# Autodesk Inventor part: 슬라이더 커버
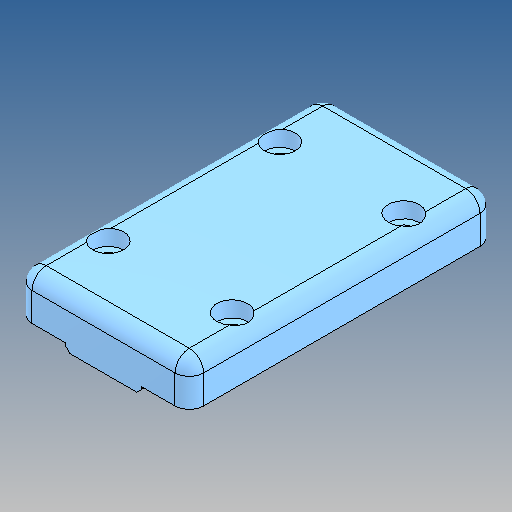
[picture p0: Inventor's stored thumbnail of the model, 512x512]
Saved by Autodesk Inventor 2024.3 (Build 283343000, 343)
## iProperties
Created: 2025-06
Part Number: 슬라이더 커버
Material: 알루미늄 6061
Document SubType Name: Modeling
Designer: user
Density: 2.7 g/cm^3
Appearance: 기본값
Author: jhkim
Sending System: Autodesk Inventor 2026
Preprocessor: ST-DEVELOPER v20.1
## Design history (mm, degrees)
node "슬라이더 커버1"
node "솔리드2"
node "솔리드1"
